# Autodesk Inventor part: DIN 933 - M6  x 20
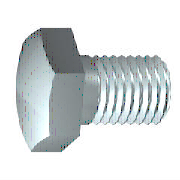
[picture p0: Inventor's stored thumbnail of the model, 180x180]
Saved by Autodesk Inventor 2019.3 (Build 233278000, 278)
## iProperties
Created: 2018-01
Part Number: DIN 933 - M6  x 20
Material: Ocel, měkká
Description: Šestihranný šroub
Document SubType Name: Modeling
Standard: DIN 933
Designer: B-hon
Standards Organization: DIN
Language: cs-CZ
Size Designation: M6  x 20
Categories: <MemberInstance><Categories><Category DisplayName="Spojovací materiál" InternalName="e4da775c-781d-43d5-af7c-5136215cf5a6" Mnemonic="FSTN"><Category DisplayName
Density: 7.85 g/cm^3
Appearance: Pololeštěná
IsCustomPart: 0
Author: B-hon
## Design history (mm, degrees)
sketch "Náčrt1"
  geometry: L1 (0, 4.35)-(0, 2.729); L2 (3, 3)-(20, 3); L3 (20, 3)-(20, 0); L4 (20, 0)-(-0.5, 0); L5 (-4.6, 0)-(24.1, 0) reference; L6 (-0.5, 0)-(-0.5, 4.35); L7 (-0.5, 4.35)-(0, 4.35); L8 (3, 3)-(2.386, 2.729); L9 (2.386, 2.729)-(0, 2.729); L10 (0, -0.87)-(0, 5.22) reference
  constraints: 16 end point, 2 collinear, 2 perpendicular, 1 parallel
  dimensions: "d0" = 20 distance between parallel lines of L3 L1 (= NLG); "d1" = 17 distance from line of L2.start L3 (= GEL); "d2" = 6 diameter of L2 L4 (= GD); "d9" = 0.5001 distance between parallel lines of L6 L1 (computed from SD); "d10" = 8.7 diameter of L7 L4 (= SD2); "d13" = 0.61355 horizontal distance of L2.start L8.end (computed from GAL); "d14" = 5.45873 diameter of L9 L4 (= BDM)
revolve "Těleso" sketch "Náčrt1" stored, may be unused: angle "d12" = 90 deg
sketch "Náčrt2"
  geometry: L1 (0, 5.774)-(5, 2.887); L2 (5, 2.887)-(5, -2.887); L3 (5, -2.887)-(0, -5.774); L4 (0, -5.774)-(-5, -2.887); L5 (-5, -2.887)-(-5, 2.887); L6 (-5, 2.887)-(0, 5.774); 2 further points
  constraints: 12 end point, 1 coincident, 1 vertical, 11 other
  dimensions: "d11" = 10 distance between parallel lines of L5 L2 (= SW)
extrude "Hlava" join sketch "Náčrt2" distance "d3" = 3.5 (= KOH - SD); taper "d4" = 0 deg
sketch "Náčrt4"
  geometry: L1 (-4, 5)-(-4, 5.774); L2 (-4, 5.774)-(-3.554, 5.774); L3 (-3.554, 5.774)-(-4, 5); L4 (-4.7, 0)-(0.2, 0) reference; L5 (-0.5, 5.774)-(-4, 5.774) reference; L6 (-4, 2.887)-(-4, 5.774) reference
  constraints: 6 end point, 2 collinear, 1 perpendicular, 1 vertical
  dimensions: "d5" = 30 deg angle of L3 L1 (= ANG1); "d19" = 10 diameter of L1.start L4 (= SW0)
revolve "Zkosení1" sketch "Náčrt4" stored, may be unused: angle "d21" = 90 deg
workplane "Work Plane1"
body "Solid1"
feature "Závit" dims "d15" = 17 (= GEL), "d16" = 0
chamfer "Zkosení2" distance "d6" = 0.61345 (= -0.5 x SPD + 0.5 x GD); stored, may be unused: second distance "d7" = 0.61355 (computed from GUL), angle "d55" = 45 deg
other parameters: "NLG" = 20 [user parameter; used in 1 equation term], "GD" = 6 (= NND) [user parameter; used in 2 equation terms], "BDM" = 5.45873 [user parameter; used in 1 equation term], "KOH" = 4 [user parameter; used in 1 equation term], "GEL" = 17 [user parameter; used in 2 equation terms], "SW" = 10 [user parameter; used in 2 equation terms], "SW0" = 10 [user parameter; used in 1 equation term], "SPD" = 4.7731 (= NND - 1.2269 x PTC) [user parameter; used in 1 equation term], "SD2" = 8.7 [user parameter; used in 1 equation term], "SD" = 0.5 [user parameter; used in 2 equation terms], "ANG1" = 30 deg [user parameter; used in 1 equation term], "GAL" = 0.61345 (= 0.61345 x PTC) [user parameter; used in 1 equation term], "GUL" = 0.61345 (= 0.61345 x PTC) [user parameter; used in 1 equation term], "d8" = 0, "RR" = 0.25 [user parameter], "d57" = 0, "d58" = 0, "GD1" = 4.7731 (= THREADDIA - 1.2269 x PTC) [user parameter], "THREADDIA" = 6 [user parameter; used in 1 equation term], "TOA" = 30 deg [user parameter], "PTC" = 1 [user parameter; used in 5 equation terms], "NND" = 6 [user parameter; used in 2 equation terms], "E0" = 11.55 (= 1.155 x SW) [user parameter]
